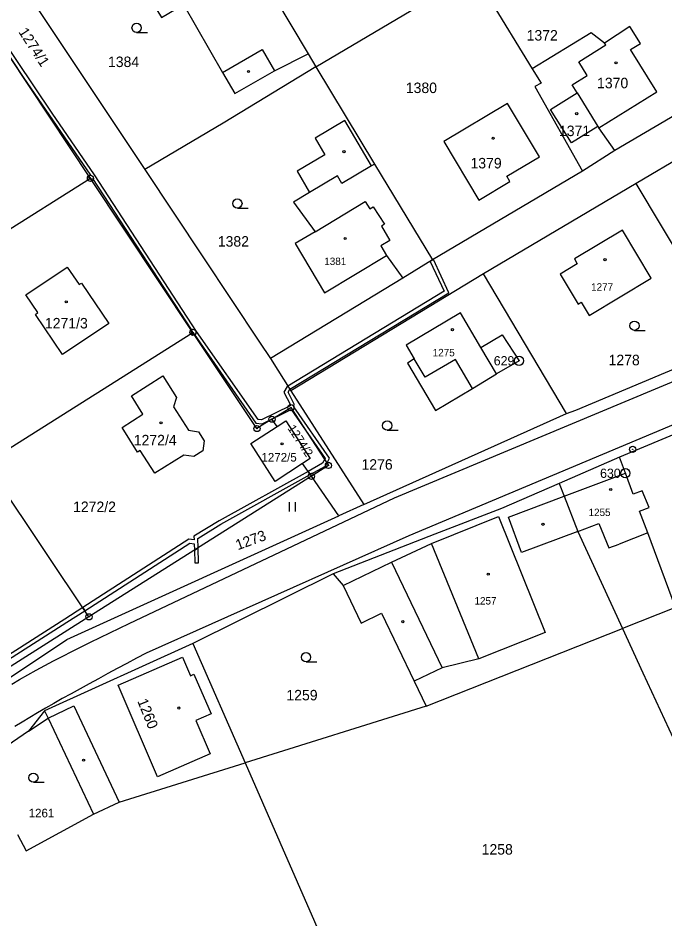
# Model space of a CAD drawing. Extents: x -504988 to -494607, y -1123820 to -1114018.
# Drawn here: x -498216.7 to -498111.8, y -1119413.1 to -1119267 of the extents above; entities that cross this region are included whole.
import ezdxf

# ---------------------------------------------------------------- set-up
doc = ezdxf.new("R2010")
doc.units = 0
for name, color, linetype in [('Hranice parcel', 7, 'Continuous'), ('Parcelní čísla', 7, 'Continuous'), ('Vnitřní kresba', 7, 'Continuous'), ('Věcná břemena k části', 7, 'Continuous'), ('Značky bodu BP', 7, 'Continuous'), ('Značky budov', 7, 'Continuous'), ('Značky kultur', 7, 'Continuous')]:
    doc.layers.add(name, color=color, linetype=linetype)

msp = doc.modelspace()

# ---------------------------------------------------------------- linework, layer by layer
at = {"layer": 'Hranice parcel'}
for p, q in [((-498186.82, -1119244.07), (-498169.68, -1119272.79)), ((-498168.4, -1119274.94), (-498142.82, -1119259.73)), ((-498142.82, -1119259.73), (-498133.3, -1119275.24)), ((-498216.21, -1119261.47), (-498196.16, -1119291.56)), ((-498169.68, -1119272.79), (-498168.4, -1119274.94)), ((-498168.4, -1119274.94), (-498158.88, -1119290.7)), ((-498098.47, -1119275.83), (-498119.92, -1119288.51)), ((-498096.22, -1119281.8), (-498116.47, -1119293.86)), ((-498119.92, -1119288.51), (-498125.15, -1119291.85)), ((-498158.88, -1119290.7), (-498149.49, -1119306.24)), ((-498125.15, -1119291.85), (-498149.49, -1119306.24)), ((-498204.98, -1119293.01), (-498238.65, -1119314.28)), ((-498188.36, -1119317.99), (-498204.98, -1119293.01)), ((-498116.47, -1119293.86), (-498141.2, -1119308.49)), ((-498100.86, -1119319.98), (-498116.47, -1119293.86)), ((-498149.49, -1119306.24), (-498154.32, -1119309.17)), ((-498154.32, -1119309.17), (-498175.78, -1119322.21)), ((-498141.2, -1119308.49), (-498172.48, -1119327.47)), ((-498127.73, -1119331.17), (-498141.2, -1119308.49)), ((-498221.94, -1119339.21), (-498188.36, -1119317.99)), ((-498177.97, -1119333.59), (-498188.36, -1119317.99)), ((-498175.78, -1119322.21), (-498172.48, -1119327.47)), ((-498172.48, -1119327.47), (-498160.61, -1119345.92)), ((-498175.53, -1119332.07), (-498172.47, -1119330.2)), ((-498099.55, -1119330.01), (-498119.18, -1119338.24)), ((-498160.61, -1119345.92), (-498127.73, -1119331.17)), ((-498175.53, -1119332.07), (-498177.97, -1119333.59)), ((-498174.71, -1119333.26), (-498175.53, -1119332.07)), ((-498174.71, -1119333.26), (-498173.3, -1119332.34)), ((-498173.3, -1119332.34), (-498169.32, -1119338.47)), ((-498178.98, -1119336.03), (-498174.71, -1119333.26)), ((-498175, -1119342.16), (-498178.98, -1119336.03)), ((-498169.32, -1119338.47), (-498170.56, -1119339.28)), ((-498119.18, -1119338.24), (-498128.96, -1119342.48)), ((-498205.22, -1119364.13), (-498221.94, -1119339.21)), ((-498170.56, -1119339.28), (-498175, -1119342.16)), ((-498169.14, -1119341.33), (-498170.56, -1119339.28)), ((-498169.14, -1119341.33), (-498205.22, -1119364.13)), ((-498164.71, -1119347.75), (-498169.14, -1119341.33)), ((-498114.36, -1119346.39), (-498115.46, -1119343.67)), ((-498160.61, -1119345.92), (-498164.71, -1119347.75)), ((-498165.6, -1119357.15), (-498188.37, -1119368.44)), ((-498110.05, -1119362.61), (-498118.69, -1119366.04)), ((-498205.22, -1119364.13), (-498239.07, -1119385.52)), ((-498150.5, -1119378.64), (-498118.69, -1119366.04)), ((-498188.37, -1119368.44), (-498212.41, -1119379.38)), ((-498188.37, -1119368.44), (-498179.9, -1119387.81)), ((-498150.5, -1119378.64), (-498179.9, -1119387.81))]:
    msp.add_line(p, q, dxfattribs=at)
for points in [[(-498192.79, -1119247.61), (-498189.94, -1119252.78), (-498198.77, -1119258.13), (-498193.44, -1119266.93), (-498189.9, -1119264.78), (-498183.54, -1119275.82), (-498181.57, -1119279.25), (-498175.12, -1119275.54), (-498169.68, -1119272.79)], [(-498204.98, -1119293.01), (-498221.61, -1119268.02), (-498255.37, -1119289.36)], [(-498119.92, -1119288.51), (-498122.5, -1119284.83), (-498113.1, -1119278.95), (-498117.37, -1119272.12), (-498115.76, -1119271.11), (-498117.47, -1119268.39), (-498121.57, -1119271.09), (-498123.74, -1119269.42), (-498133.3, -1119275.24)], [(-498168.4, -1119274.94), (-498183.44, -1119284.08), (-498196.16, -1119291.56)], [(-498133.3, -1119275.24), (-498131.88, -1119277.55), (-498132.9, -1119278.12), (-498125.15, -1119291.85)], [(-498126.05, -1119279.15), (-498122.66, -1119284.57), (-498126.95, -1119287.26), (-498130.35, -1119281.83), (-498126.05, -1119279.15)], [(-498137.32, -1119280.86), (-498147.66, -1119287.04), (-498141.98, -1119296.54), (-498136.93, -1119293.53), (-498137.45, -1119292.67), (-498132.16, -1119289.51), (-498137.32, -1119280.86)], [(-498158.88, -1119290.7), (-498159.37, -1119290.99), (-498163.72, -1119283.64), (-498168.53, -1119286.48), (-498166.94, -1119289.18), (-498171.47, -1119291.86), (-498169.43, -1119295.3), (-498172.02, -1119296.87), (-498168.55, -1119301.66), (-498171.77, -1119303.59), (-498166.99, -1119311.56), (-498156.95, -1119305.53), (-498154.32, -1119309.17)], [(-498196.16, -1119291.56), (-498186.77, -1119305.76), (-498177.56, -1119319.56), (-498175.78, -1119322.21)], [(-498124.08, -1119315.25), (-498114, -1119309.21), (-498118.68, -1119301.41), (-498126.48, -1119306.08), (-498126.01, -1119306.86), (-498128.8, -1119308.53), (-498125.89, -1119313.4), (-498125.37, -1119313.09), (-498124.08, -1119315.25)], [(-498215.44, -1119311.88), (-498208.76, -1119307.39), (-498206.83, -1119310.21), (-498206.41, -1119309.98), (-498202.02, -1119316.53), (-498209.49, -1119321.59), (-498213.9, -1119315.07), (-498213.52, -1119314.78), (-498215.44, -1119311.88)], [(-498144.97, -1119314.83), (-498153.78, -1119320.06), (-498152.46, -1119322.3), (-498153.57, -1119322.96), (-498149, -1119330.67), (-498142.98, -1119327.09), (-498139.09, -1119324.73), (-498141.64, -1119320.43), (-498144.97, -1119314.83)], [(-498127.73, -1119331.17), (-498126.26, -1119330.6), (-498100.86, -1119319.98)], [(-498189.09, -1119333.84), (-498187.45, -1119334.14), (-498186.55, -1119335.56), (-498186.75, -1119337.22), (-498188.2, -1119338.14), (-498189.85, -1119337.89), (-498194.52, -1119340.84), (-498196.9, -1119337.17), (-498197.32, -1119337.42), (-498199.85, -1119333.4), (-498196.47, -1119331.25), (-498198.34, -1119328.3), (-498193.23, -1119325.06), (-498191, -1119328.53), (-498191.49, -1119330.05), (-498189.09, -1119333.84)], [(-498172.47, -1119330.2), (-498166.37, -1119339.58), (-498169.14, -1119341.33)], [(-498115.46, -1119343.67), (-498116.95, -1119344.21), (-498118.21, -1119340.84), (-498119.18, -1119338.24)], [(-498128.96, -1119342.48), (-498138.3, -1119346.54), (-498149.1, -1119350.71), (-498165.6, -1119357.15)], [(-498128.96, -1119342.48), (-498128.15, -1119344.57), (-498125.93, -1119350.27), (-498118.69, -1119366.04)], [(-498237.95, -1119387.19), (-498208.83, -1119367.83), (-498164.71, -1119347.75)], [(-498110.05, -1119362.61), (-498114.58, -1119350.52), (-498115.9, -1119346.99), (-498114.36, -1119346.39)], [(-498165.6, -1119357.15), (-498163.99, -1119359.05), (-498161.07, -1119365.13), (-498157.74, -1119363.53), (-498152.44, -1119374.58), (-498150.5, -1119378.64)], [(-498118.69, -1119366.04), (-498115.4, -1119373.2), (-498099.2, -1119408.01)], [(-498212.41, -1119379.38), (-498215.02, -1119382.69), (-498222.86, -1119388.01)], [(-498212.41, -1119379.38), (-498211.86, -1119380.55), (-498204.5, -1119396.16)], [(-498204.5, -1119396.16), (-498200.31, -1119394.18), (-498179.9, -1119387.81)], [(-498179.9, -1119387.81), (-498160.2, -1119432.86), (-498158.65, -1119435.77)], [(-498216.82, -1119399.43), (-498215.41, -1119402.08), (-498204.5, -1119396.16)]]:
    msp.add_lwpolyline(points, dxfattribs=at)
at = {"layer": 'Vnitřní kresba'}
for p, q in [((-498125.77, -1119274.1), (-498121.4, -1119271.37)), ((-498121.4, -1119271.37), (-498121.57, -1119271.09)), ((-498183.54, -1119275.82), (-498177.1, -1119272.11)), ((-498177.1, -1119272.11), (-498175.12, -1119275.54)), ((-498124.39, -1119276.31), (-498125.77, -1119274.1)), ((-498126.86, -1119277.86), (-498124.39, -1119276.31)), ((-498126.05, -1119279.15), (-498126.86, -1119277.86)), ((-498122.66, -1119284.57), (-498122.5, -1119284.83)), ((-498159.37, -1119290.99), (-498164.19, -1119293.84)), ((-498164.91, -1119292.62), (-498169.43, -1119295.3)), ((-498164.19, -1119293.84), (-498164.91, -1119292.62)), ((-498168.55, -1119301.66), (-498160.39, -1119296.77)), ((-498160.39, -1119296.77), (-498159.67, -1119297.97)), ((-498159.67, -1119297.97), (-498159.11, -1119297.63)), ((-498159.11, -1119297.63), (-498157.3, -1119300.46)), ((-498157.3, -1119300.46), (-498157.78, -1119300.74)), ((-498157.78, -1119300.74), (-498156.39, -1119303.06)), ((-498155.67, -1119344.84), (-498048.67, -1119300.09)), ((-498156.39, -1119303.06), (-498157.89, -1119303.96)), ((-498157.89, -1119303.96), (-498156.95, -1119305.53)), ((-498046.12, -1119305.93), (-498153.33, -1119350.99)), ((-498141.64, -1119320.43), (-498138.2, -1119318.39)), ((-498138.2, -1119318.39), (-498135.46, -1119322.59)), ((-498150.69, -1119325.28), (-498152.46, -1119322.3)), ((-498145.78, -1119322.37), (-498150.69, -1119325.28)), ((-498142.98, -1119327.09), (-498145.78, -1119322.37)), ((-498135.46, -1119322.59), (-498139.09, -1119324.73)), ((-498128.15, -1119344.57), (-498118.21, -1119340.84)), ((-498198.7, -1119365.2), (-498155.67, -1119344.84)), ((-498137.19, -1119347.96), (-498128.15, -1119344.57)), ((-498149.68, -1119352.22), (-498138.81, -1119347.88)), ((-498138.81, -1119347.88), (-498131.22, -1119366.66)), ((-498135.04, -1119353.68), (-498137.19, -1119347.96)), ((-498125.93, -1119350.27), (-498122.5, -1119348.98)), ((-498122.5, -1119348.98), (-498120.89, -1119352.96)), ((-498125.93, -1119350.27), (-498135.04, -1119353.68)), ((-498114.58, -1119350.52), (-498119.23, -1119352.32)), ((-498153.33, -1119350.99), (-498195.95, -1119370.01)), ((-498156.14, -1119355.28), (-498149.68, -1119352.22)), ((-498141.99, -1119370.93), (-498149.68, -1119352.22)), ((-498120.89, -1119352.96), (-498119.23, -1119352.32)), ((-498163.99, -1119359.05), (-498156.14, -1119355.28)), ((-498156.14, -1119355.28), (-498147.93, -1119372.42)), ((-498131.22, -1119366.66), (-498141.99, -1119370.93)), ((-498200.5, -1119375.23), (-498190.06, -1119370.66)), ((-498190.06, -1119370.66), (-498188.74, -1119373.68)), ((-498141.99, -1119370.93), (-498147.93, -1119372.42)), ((-498147.93, -1119372.42), (-498152.44, -1119374.58)), ((-498188.74, -1119373.68), (-498188.18, -1119373.44)), ((-498188.18, -1119373.44), (-498185.37, -1119379.87)), ((-498194.1, -1119390.08), (-498200.5, -1119375.23)), ((-498211.86, -1119380.55), (-498207.67, -1119378.58)), ((-498207.67, -1119378.58), (-498200.31, -1119394.18)), ((-498185.37, -1119379.87), (-498187.87, -1119380.96)), ((-498215.02, -1119382.69), (-498211.86, -1119380.55)), ((-498187.87, -1119380.96), (-498185.54, -1119386.33)), ((-498185.54, -1119386.33), (-498194.1, -1119390.08))]:
    msp.add_line(p, q, dxfattribs=at)
for points in [[(-498217.73, -1119375.03), (-498216.46, -1119374.28), (-498215.15, -1119373.53), (-498213.78, -1119372.76), (-498212.38, -1119372.01), (-498210.96, -1119371.25), (-498209.48, -1119370.49), (-498208, -1119369.74), (-498206.49, -1119368.98), (-498204.94, -1119368.22), (-498203.4, -1119367.47), (-498201.85, -1119366.72), (-498200.27, -1119365.95), (-498198.7, -1119365.2)], [(-498195.95, -1119370.01), (-498197.51, -1119370.84), (-498199.08, -1119371.68), (-498200.62, -1119372.51), (-498202.15, -1119373.33), (-498203.69, -1119374.16), (-498205.18, -1119374.98), (-498206.66, -1119375.79), (-498208.12, -1119376.6), (-498209.54, -1119377.39), (-498210.92, -1119378.18), (-498212.27, -1119378.96), (-498213.57, -1119379.72), (-498214.82, -1119380.47), (-498216.05, -1119381.22), (-498217.22, -1119381.94)]]:
    msp.add_lwpolyline(points, dxfattribs=at)
at = {"layer": 'Věcná břemena k části'}
msp.add_lwpolyline([(-498221.61, -1119268.02), (-498215.91, -1119276.58), (-498204.99, -1119292.51), (-498205.23, -1119292.64), (-498204.98, -1119293.01), (-498204.89, -1119293.14), (-498204.65, -1119293.01), (-498188.66, -1119317.54), (-498188.36, -1119317.99), (-498188.16, -1119318.29), (-498178.13, -1119332.71), (-498177.12, -1119332.8), (-498172.43, -1119330.49), (-498166.89, -1119338.42), (-498167.31, -1119339.23), (-498169.68, -1119340.55), (-498169.34, -1119341.04), (-498166.87, -1119339.67), (-498166.19, -1119338.38), (-498172.01, -1119330.05), (-498171.91, -1119329.64), (-498172.9, -1119327.68), (-498172.64, -1119327.22), (-498146.85, -1119311.55), (-498149.34, -1119306.15), (-498149.86, -1119306.47), (-498147.61, -1119311.31), (-498172.96, -1119326.71), (-498173.07, -1119326.78), (-498173.58, -1119327.66), (-498172.55, -1119329.72), (-498172.59, -1119329.9), (-498177.24, -1119332.18), (-498177.79, -1119332.13), (-498187.75, -1119317.82), (-498204.3, -1119292.45), (-498211.17, -1119282.43), (-498225.65, -1119260.88)], dxfattribs=at)
for points in [[(-498205.34, -1119292.69), (-498205.12, -1119293.1), (-498204.98, -1119293.01), (-498205.23, -1119292.64)], [(-498188.66, -1119317.54), (-498188.66, -1119318.18), (-498188.36, -1119317.99)], [(-498188.16, -1119318.29), (-498188.36, -1119317.99), (-498188.66, -1119318.18), (-498188.66, -1119318.29)], [(-498205.88, -1119363.14), (-498188.88, -1119352.16), (-498188.15, -1119352.27), (-498188.11, -1119353.32), (-498187.52, -1119352.95), (-498187.58, -1119351.4), (-498183.82, -1119349.08), (-498169.34, -1119341.04), (-498169.68, -1119340.55), (-498184.12, -1119348.56), (-498188.2, -1119351.07), (-498188.17, -1119351.66), (-498189.02, -1119351.54), (-498206.22, -1119362.64)], [(-498187.52, -1119352.95), (-498188.11, -1119353.32), (-498188.03, -1119355.38), (-498187.43, -1119355.36)], [(-498240.79, -1119382.95), (-498240.44, -1119383.47), (-498234.71, -1119381.53), (-498208.79, -1119365.01), (-498205.88, -1119363.14), (-498206.22, -1119362.64), (-498209.11, -1119364.51), (-498234.97, -1119380.99)]]:
    msp.add_lwpolyline(points, close=True, dxfattribs=at)
at = {"layer": 'Značky bodu BP'}
for centre, radius in [((-498204.98, -1119293.01), 0.5), ((-498204.98, -1119293.01), 0.0303), ((-498188.36, -1119317.99), 0.5), ((-498188.36, -1119317.99), 0.0303), ((-498135.46, -1119322.59), 0.75), ((-498135.46, -1119322.59), 0.03), ((-498172.47, -1119330.2), 0.5), ((-498172.47, -1119330.2), 0.0303), ((-498175.53, -1119332.07), 0.5), ((-498177.97, -1119333.59), 0.5), ((-498175.53, -1119332.07), 0.0303), ((-498177.97, -1119333.59), 0.0303), ((-498117.02, -1119336.97), 0.5), ((-498117.02, -1119336.97), 0.0303), ((-498166.37, -1119339.58), 0.5), ((-498166.37, -1119339.58), 0.0303), ((-498118.21, -1119340.84), 0.75), ((-498169.14, -1119341.33), 0.5), ((-498169.14, -1119341.33), 0.0303), ((-498118.21, -1119340.84), 0.03), ((-498205.22, -1119364.13), 0.5), ((-498205.22, -1119364.13), 0.0303)]:
    msp.add_circle(centre, radius, dxfattribs=at)
at = {"layer": 'Značky budov'}
for centre in [(-498119.72, -1119274.27), (-498179.34, -1119275.67), (-498126.1, -1119282.51), (-498139.66, -1119286.5), (-498163.85, -1119288.67), (-498163.65, -1119302.75), (-498121.5, -1119306.2), (-498208.9, -1119313.03), (-498146.26, -1119317.56), (-498193.53, -1119332.65), (-498173.89, -1119336.06), (-498120.58, -1119343.48), (-498131.57, -1119349.11), (-498140.45, -1119357.22), (-498154.3, -1119364.92), (-498190.63, -1119378.93), (-498206.09, -1119387.37)]:
    msp.add_circle(centre, 0.175, dxfattribs=at)
at = {"layer": 'Značky kultur'}
for p, q in [((-498197.49, -1119269.34), (-498195.74, -1119269.34)), ((-498181.14, -1119297.83), (-498179.39, -1119297.83)), ((-498116.74, -1119317.66), (-498114.99, -1119317.66)), ((-498156.83, -1119333.85), (-498155.08, -1119333.85)), ((-498172.71, -1119347.02), (-498172.71, -1119345.52)), ((-498171.71, -1119347.02), (-498171.71, -1119345.52)), ((-498170.01, -1119371.43), (-498168.26, -1119371.43)), ((-498214.23, -1119390.97), (-498212.48, -1119390.97))]:
    msp.add_line(p, q, dxfattribs=at)
for centre in [(-498197.49, -1119268.59), (-498181.14, -1119297.08), (-498116.74, -1119316.91), (-498156.83, -1119333.1), (-498170.01, -1119370.68), (-498214.23, -1119390.22)]:
    msp.add_circle(centre, 0.75, dxfattribs=at)

# ---------------------------------------------------------------- texts
at = {"layer": 'Parcelní čísla'}
for s, height, rotation, p in [('1274/1', 1.7, 303, (-498216.72, -1119269.24)), ('1274/2', 1.4, 303, (-498173.06, -1119333.54)), ('1273', 1.7, 20, (-498181.07, -1119353.34)), ('1260', 1.7, 292, (-498197.4, -1119377.79))]:
    msp.add_text(s, height=height, rotation=rotation, dxfattribs=at).set_placement(p)
for s, height, p in [('1372', 1.7, (-498134.22, -1119270.65)), ('1384', 1.7, (-498202.13, -1119274.95)), ('1380', 1.7, (-498153.82, -1119279.17)), ('1370', 1.7, (-498122.8, -1119278.39)), ('1371', 1.7, (-498128.98, -1119286.15)), ('1379', 1.7, (-498143.33, -1119291.39)), ('1382', 1.7, (-498184.32, -1119304.08)), ('1381', 1.2, (-498167.05, -1119307.06)), ('1277', 1.2, (-498123.76, -1119311.22)), ('1271/3', 1.7, (-498212.36, -1119317.35)), ('1275', 1.2, (-498149.46, -1119321.87)), ('1278', 1.7, (-498120.93, -1119323.32)), ('1272/4', 1.7, (-498197.95, -1119336.31)), ('1272/5', 1.4, (-498177.24, -1119338.95)), ('1276', 1.7, (-498161.01, -1119340.26)), ('1272/2', 1.7, (-498207.79, -1119347.13)), ('1255', 1.2, (-498124.18, -1119347.78)), ('1257', 1.2, (-498142.68, -1119362.13)), ('1259', 1.7, (-498173.19, -1119377.68)), ('1261', 1.4, (-498215, -1119396.66)), ('1258', 1.7, (-498141.52, -1119402.7))]:
    msp.add_text(s, height=height, dxfattribs=at).set_placement(p)
at = {"layer": 'Značky bodu BP'}
for s, p in [('629', (-498139.56, -1119323.34)), ('630', (-498122.31, -1119341.59))]:
    msp.add_text(s, height=1.5, dxfattribs=at).set_placement(p)

doc.saveas('drawing.dxf')
